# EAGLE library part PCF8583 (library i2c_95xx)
Clock/calendar with 240 x 8-bit RAM
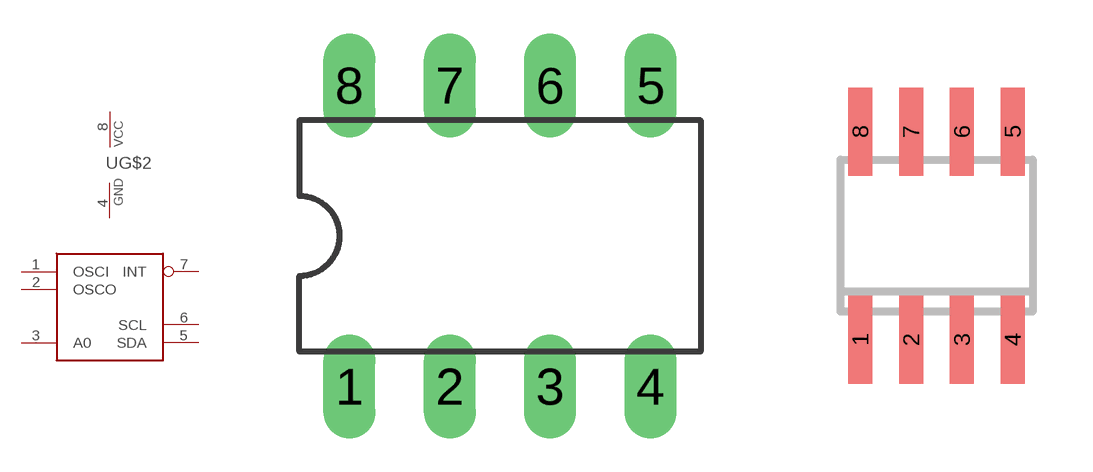
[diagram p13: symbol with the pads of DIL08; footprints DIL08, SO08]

Designator prefix -; gates G$1=PCF8583 G$2=PWRN

## PCF8583P  [DIL08]
1  G$1:OSCI  in
2  G$1:OSCO  out
3  G$1:A0  in
4  G$2:GND  pwr
5  G$1:SDA
6  G$1:SCL  in
7  G$1:INT  out
8  G$2:VCC  pwr

## PCF8583T  [SO08]
Pads as for DIL08

## Footprint DIL08 (pad centres in mm)
drill 0.813 long: 1 -3.81,-3.81; 2 -1.27,-3.81; 3 1.27,-3.81; 4 3.81,-3.81; 5 3.81,3.81; 6 1.27,3.81; 7 -1.27,3.81; 8 -3.81,3.81

## Footprint SO08 (pad centres in mm)
smd 0.6 x 2.2: 1 -1.905,-2.6; 2 -0.635,-2.6; 3 0.635,-2.6; 4 1.905,-2.6; 5 1.905,2.6; 6 0.635,2.6; 7 -0.635,2.6; 8 -1.905,2.6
